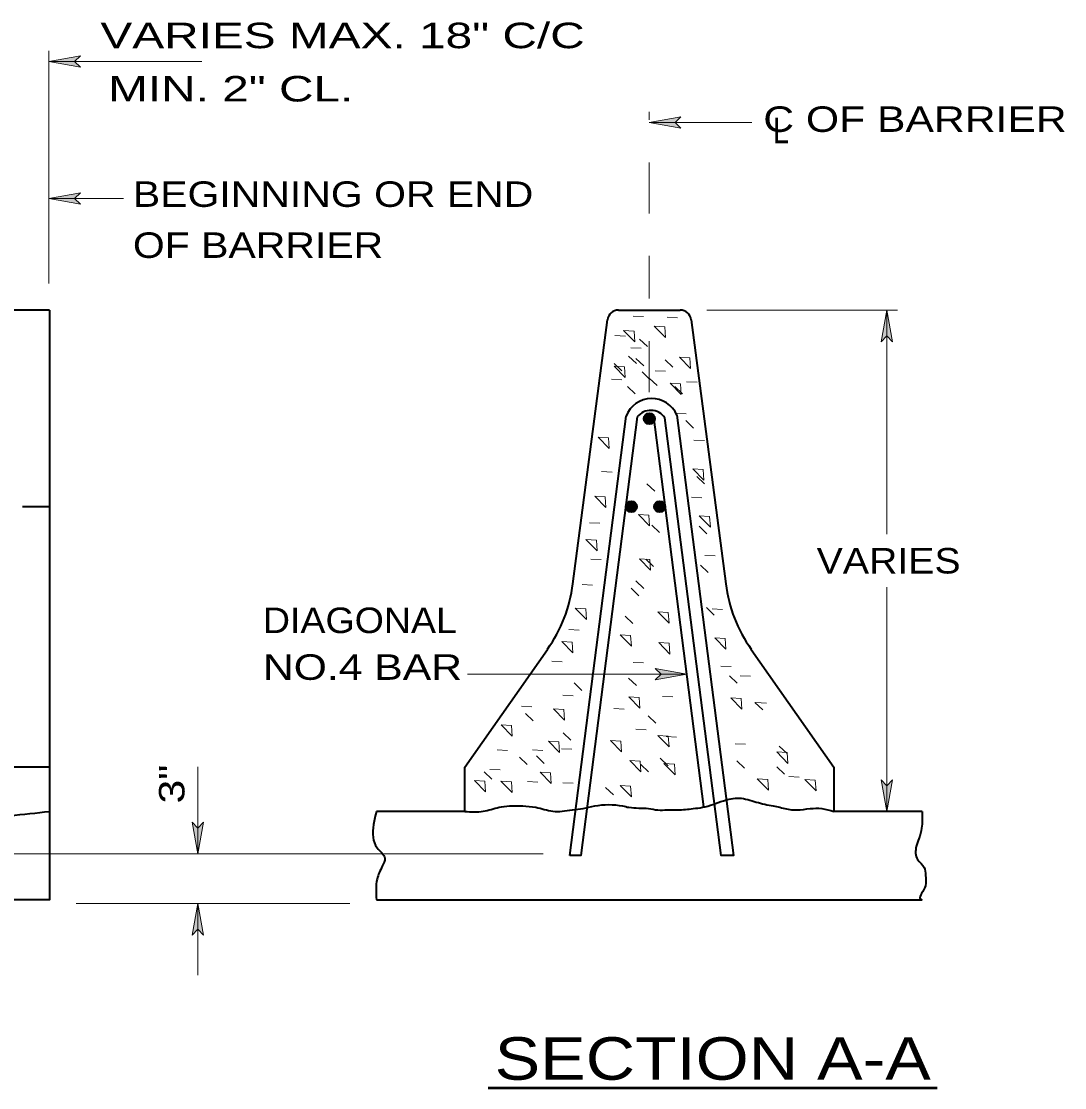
# Model space of a CAD drawing. Extents: x -111.57 to -104.56, y -202.94 to -194.51.
# Drawn here: x -107.008 to -104.555, y -197.601 to -195.094 of the extents above; entities that cross this region are included whole.
import ezdxf
from ezdxf.enums import TextEntityAlignment as Align

# ---------------------------------------------------------------- set-up
doc = ezdxf.new("R2010")
doc.units = 0
doc.header["$LTSCALE"] = 0.024
doc.linetypes.add('DOT_DASHED', pattern=[7.7, 5, -1.2, 0.3, -1.2])
for name, color, linetype, lineweight in [('1', 7, 'Continuous', 35), ('10', 7, 'Continuous', 13), ('12', 7, 'Continuous', 53), ('6', 7, 'Continuous', 13)]:
    doc.layers.add(name, color=color, linetype=linetype, lineweight=lineweight)

msp = doc.modelspace()

# ---------------------------------------------------------------- hatches: boundary and pattern name
at = {"layer": '1'}
for points in [[(-105.51865, -196.02796, 1), (-105.54452, -196.02796, 1)], [(-105.56086, -196.235, 1), (-105.58672, -196.235, 1)], [(-105.49432, -196.235, 1), (-105.52018, -196.235, 1)]]:
    msp.add_hatch(color=256, dxfattribs=at).paths.add_polyline_path(points)
at = {"layer": '10'}
for points in [[(-106.86883, -195.20133), (-106.94333, -195.18817), (-106.86883, -195.175), (-106.883, -195.18817)], [(-105.45717, -195.3445), (-105.53167, -195.33133), (-105.45717, -195.31817), (-105.47117, -195.33133)], [(-106.86883, -195.5235), (-106.94333, -195.51033), (-106.86883, -195.49717), (-106.883, -195.51033)], [(-104.98633, -195.847), (-104.97317, -195.77267), (-104.96, -195.847), (-104.97317, -195.833)], [(-105.518, -196.61567), (-105.4435, -196.62883), (-105.518, -196.642), (-105.504, -196.62883)], [(-104.98633, -196.87717), (-104.97317, -196.95167), (-104.96, -196.87717), (-104.97317, -196.89133)], [(-106.58, -196.97717), (-106.593, -197.05167), (-106.60617, -196.97717), (-106.593, -196.99117)], [(-106.60617, -197.24233), (-106.593, -197.168), (-106.58, -197.24233), (-106.593, -197.22833)]]:
    msp.add_hatch(color=256, dxfattribs=at).paths.add_polyline_path(points)

# ---------------------------------------------------------------- linework, layer by layer
at = {"layer": '1'}
for p, q in [((-106.9415, -195.77267), (-111.493, -195.77267)), ((-105.60417, -195.77267), (-105.459, -195.77267)), ((-105.71133, -196.41667), (-105.63, -195.79533)), ((-105.43317, -195.79533), (-105.35183, -196.4165)), ((-105.71883, -197.05567), (-105.58617, -196.022)), ((-106.9415, -196.235), (-107.00533, -196.235)), ((-106.9415, -196.84767), (-111.493, -196.84767)), ((-105.96517, -196.95167), (-106.17317, -196.95167)), ((-104.89017, -196.95167), (-105.09817, -196.95167)), ((-106.17317, -197.15983), (-104.89017, -197.15983))]:
    msp.add_line(p, q, dxfattribs=at)
for points in [[(-106.9415, -195.77267), (-106.9415, -197.15983), (-111.493, -197.15983)], [(-105.56, -196.024), (-105.6925, -197.05567), (-105.71883, -197.05567)], [(-105.46683, -196.01967), (-105.33383, -197.05567), (-105.36283, -197.05567), (-105.495, -196.02617)], [(-105.96517, -196.95167), (-105.96517, -196.84767), (-105.77117, -196.5705)], [(-105.29217, -196.5705), (-105.09817, -196.84767), (-105.09817, -196.95167)]]:
    msp.add_lwpolyline(points, dxfattribs=at)
for centre in [(-105.53158, -196.02796), (-105.57379, -196.235), (-105.50725, -196.235)]:
    msp.add_circle(centre, 0.01293, dxfattribs=at)
for centre, radius, start, end in [((-105.60414, -195.79863), 0.02601, 90, 172.54564), ((-105.45906, -195.79863), 0.02601, 7.46293, 90), ((-105.526, -196.04516), 0.06446, 23.1931, 158.88304), ((-105.52831, -196.04879), 0.04024, 34.0471, 142.14754), ((-106.05514, -196.3716), 0.34678, 325.01261, 352.53254), ((-105.00805, -196.37159), 0.34678, 187.4588, 214.99795)]:
    msp.add_arc(centre, radius, start, end, dxfattribs=at)
for points in [[(-110.89483, -196.95167), (-110.80983, -196.9485), (-110.77133, -196.93583), (-110.73283, -196.9315), (-110.70733, -196.94417), (-110.68167, -196.95267), (-110.66033, -196.95267), (-110.639, -196.9485), (-110.61333, -196.94417), (-110.5835, -196.94), (-110.54933, -196.94), (-110.528, -196.94), (-110.50667, -196.9485), (-110.45967, -196.9485), (-110.42117, -196.9485), (-110.36567, -196.93583), (-110.323, -196.9315), (-110.29317, -196.92717), (-110.28033, -196.94), (-110.2505, -196.95267), (-110.19483, -196.95267), (-110.15217, -196.9485), (-110.08817, -196.93583), (-110.02417, -196.92717), (-109.99417, -196.9315), (-109.96433, -196.94), (-109.88317, -196.9485), (-109.84483, -196.94417), (-109.81483, -196.93583), (-109.768, -196.92717), (-109.704, -196.923), (-109.67817, -196.92717), (-109.6185, -196.93583), (-109.56717, -196.94417), (-109.49033, -196.9485), (-109.42633, -196.95267), (-109.34517, -196.94417), (-109.28967, -196.94417), (-109.22567, -196.9315), (-109.1615, -196.923), (-109.11033, -196.923), (-109.02067, -196.93583), (-108.93533, -196.94417), (-108.8585, -196.9485), (-108.773, -196.9485), (-108.70467, -196.9485), (-108.615, -196.94), (-108.52967, -196.92717), (-108.46133, -196.9145), (-108.376, -196.9315), (-108.30767, -196.94), (-108.21783, -196.94417), (-108.1155, -196.94), (-108.03433, -196.93583), (-107.966, -196.9315), (-107.902, -196.92717), (-107.82083, -196.91867), (-107.76533, -196.92717), (-107.71833, -196.93583), (-107.63717, -196.94417), (-107.54333, -196.94), (-107.50483, -196.9315), (-107.45367, -196.923), (-107.411, -196.923), (-107.31267, -196.9315), (-107.23583, -196.94417), (-107.159, -196.96117), (-107.03517, -196.96117), (-106.9415, -196.95167)], [(-105.96517, -196.95167), (-105.922, -196.95117), (-105.88483, -196.942), (-105.86033, -196.93883), (-105.82933, -196.93883), (-105.7985, -196.942), (-105.75833, -196.95117), (-105.73683, -196.95117), (-105.71217, -196.94817), (-105.68733, -196.945), (-105.65967, -196.93883), (-105.59483, -196.93883), (-105.5795, -196.942), (-105.53317, -196.945), (-105.51167, -196.94817), (-105.49, -196.94817), (-105.46533, -196.94817), (-105.42833, -196.945), (-105.40667, -196.942), (-105.35733, -196.92667), (-105.32033, -196.92033), (-105.28017, -196.92967), (-105.24017, -196.93883), (-105.22467, -196.942), (-105.19383, -196.94817), (-105.18467, -196.94817), (-105.15367, -196.945), (-105.126, -196.945), (-105.09817, -196.95167)]]:
    msp.add_spline(points, degree=3, dxfattribs=at)
at = {"layer": '10'}
for p, q in [((-106.94333, -195.71017), (-106.94333, -195.16317)), ((-106.94333, -195.18817), (-106.86883, -195.175)), ((-106.94333, -195.18817), (-106.58333, -195.18817)), ((-106.94333, -195.18817), (-106.86883, -195.20133)), ((-105.53167, -195.33133), (-105.45717, -195.31817)), ((-105.29067, -195.33133), (-105.53167, -195.33133)), ((-105.53167, -195.33133), (-105.45717, -195.3445)), ((-106.94333, -195.51033), (-106.86883, -195.49717)), ((-106.94333, -195.51033), (-106.76817, -195.51033)), ((-106.94333, -195.51033), (-106.86883, -195.5235)), ((-105.3965, -195.77267), (-104.94817, -195.77267)), ((-104.97317, -195.77267), (-104.98633, -195.847)), ((-104.97317, -195.77267), (-104.96, -195.847)), ((-104.97317, -196.29967), (-104.97317, -195.77267)), ((-104.97317, -196.95167), (-104.97317, -196.42467)), ((-105.4435, -196.62883), (-105.518, -196.61567)), ((-105.959, -196.62883), (-105.4435, -196.62883)), ((-105.4435, -196.62883), (-105.518, -196.642)), ((-106.593, -197.05167), (-106.593, -196.84683)), ((-104.97317, -196.95167), (-104.98633, -196.87717)), ((-104.97317, -196.95167), (-104.96, -196.87717)), ((-106.593, -197.05167), (-106.60617, -196.97717)), ((-106.593, -197.05167), (-106.58, -196.97717)), ((-107.08717, -197.05167), (-105.78133, -197.05167)), ((-106.879, -197.168), (-106.23567, -197.168)), ((-106.593, -197.168), (-106.60617, -197.24233)), ((-106.593, -197.168), (-106.593, -197.33667)), ((-106.593, -197.168), (-106.58, -197.24233))]:
    msp.add_line(p, q, dxfattribs=at)
at = {"layer": '10', "linetype": 'DOT_DASHED'}
msp.add_line((-105.53167, -195.9655), (-105.53167, -195.30633), dxfattribs=at)
at = {"layer": '10', "lineweight": 35}
msp.add_line((-105.4035, -196.94117), (-105.52183, -196.01733), dxfattribs=at)
at = {"layer": '10'}
for points in [[(-106.86883, -195.20133), (-106.94333, -195.18817), (-106.86883, -195.175), (-106.883, -195.18817)], [(-105.45717, -195.3445), (-105.53167, -195.33133), (-105.45717, -195.31817), (-105.47117, -195.33133)], [(-106.86883, -195.5235), (-106.94333, -195.51033), (-106.86883, -195.49717), (-106.883, -195.51033)], [(-104.98633, -195.847), (-104.97317, -195.77267), (-104.96, -195.847), (-104.97317, -195.833)], [(-105.518, -196.61567), (-105.4435, -196.62883), (-105.518, -196.642), (-105.504, -196.62883)], [(-104.98633, -196.87717), (-104.97317, -196.95167), (-104.96, -196.87717), (-104.97317, -196.89133)], [(-106.58, -196.97717), (-106.593, -197.05167), (-106.60617, -196.97717), (-106.593, -196.99117)], [(-106.60617, -197.24233), (-106.593, -197.168), (-106.58, -197.24233), (-106.593, -197.22833)]]:
    msp.add_lwpolyline(points, close=True, dxfattribs=at)
for points in [[(-106.86883, -195.20133), (-106.883, -195.18817), (-106.86883, -195.175)], [(-105.45717, -195.3445), (-105.47117, -195.33133), (-105.45717, -195.31817)], [(-106.86883, -195.5235), (-106.883, -195.51033), (-106.86883, -195.49717)], [(-104.98633, -195.847), (-104.97317, -195.833), (-104.96, -195.847)], [(-105.518, -196.61567), (-105.504, -196.62883), (-105.518, -196.642)], [(-104.98633, -196.87717), (-104.97317, -196.89133), (-104.96, -196.87717)], [(-106.58, -196.97717), (-106.593, -196.99117), (-106.60617, -196.97717)], [(-106.60617, -197.24233), (-106.593, -197.22833), (-106.58, -197.24233)]]:
    msp.add_lwpolyline(points, dxfattribs=at)
at = {"layer": '10', "lineweight": 35}
for points in [[(-106.17317, -196.95167), (-106.181, -197.01267), (-106.17167, -197.03717), (-106.15333, -197.06183), (-106.15933, -197.08033), (-106.17167, -197.111), (-106.17317, -197.15983)], [(-104.89017, -196.95167), (-104.8915, -196.99117), (-104.89767, -197.01583), (-104.904, -197.03417), (-104.90083, -197.06483), (-104.88533, -197.08333), (-104.88233, -197.10183), (-104.88233, -197.1265), (-104.8915, -197.14483), (-104.89467, -197.15717), (-104.89017, -197.15983)]]:
    msp.add_spline(points, degree=3, dxfattribs=at)
at = {"layer": '12'}
msp.add_line((-105.91017, -197.60133), (-104.855, -197.60133), dxfattribs=at)
at = {"layer": '6'}
for p, q in [((-105.545, -195.788), (-105.5695, -195.78683)), ((-105.465, -195.79083), (-105.4895, -195.78967)), ((-105.58783, -195.83383), (-105.61233, -195.83267)), ((-105.53617, -195.8585), (-105.5545, -195.841)), ((-105.55067, -195.86233), (-105.57517, -195.86117)), ((-105.59617, -195.91567), (-105.6145, -195.89817)), ((-105.56183, -195.8985), (-105.58017, -195.881)), ((-105.54467, -195.90417), (-105.563, -195.88667)), ((-105.47617, -195.90717), (-105.4945, -195.88967)), ((-105.5305, -195.93567), (-105.54867, -195.91817)), ((-105.49367, -195.91667), (-105.518, -195.9155)), ((-105.5965, -195.93667), (-105.62083, -195.9355)), ((-105.51333, -195.95), (-105.53167, -195.9325)), ((-105.41933, -195.94233), (-105.44383, -195.94117)), ((-105.56467, -195.97), (-105.583, -195.9525)), ((-105.45333, -195.97), (-105.47167, -195.9525)), ((-105.445, -196.01667), (-105.4695, -196.0155)), ((-105.42767, -196.05), (-105.446, -196.0325)), ((-105.40217, -196.0795), (-105.42667, -196.07833)), ((-105.61933, -196.15383), (-105.64367, -196.15267)), ((-105.402, -196.1815), (-105.42017, -196.164)), ((-105.519, -196.1985), (-105.53733, -196.181)), ((-105.408, -196.21383), (-105.43233, -196.21267)), ((-105.64783, -196.27383), (-105.67217, -196.27267)), ((-105.50767, -196.29567), (-105.52583, -196.27817)), ((-105.39617, -196.29867), (-105.4145, -196.28117)), ((-105.3765, -196.351), (-105.401, -196.34983)), ((-105.645, -196.3595), (-105.66933, -196.35833)), ((-105.52183, -196.37567), (-105.54017, -196.35817)), ((-105.39333, -196.39), (-105.41167, -196.3725)), ((-105.665, -196.4195), (-105.68933, -196.41833)), ((-105.55617, -196.44433), (-105.5745, -196.42683)), ((-105.54467, -196.42717), (-105.563, -196.40967)), ((-105.379, -196.49), (-105.39733, -196.4725)), ((-105.35933, -196.47667), (-105.38383, -196.4755)), ((-105.5705, -196.51), (-105.58867, -196.4925)), ((-105.69633, -196.52533), (-105.72083, -196.52417)), ((-105.73633, -196.59967), (-105.76083, -196.5985)), ((-105.545, -196.6025), (-105.5695, -196.60133)), ((-105.33933, -196.611), (-105.36383, -196.60983)), ((-105.69033, -196.66717), (-105.70867, -196.64967)), ((-105.56183, -196.65583), (-105.58017, -196.63833)), ((-105.32483, -196.65), (-105.34317, -196.6325)), ((-105.29367, -196.63383), (-105.31817, -196.63267)), ((-105.71067, -196.67967), (-105.735, -196.6785)), ((-105.4765, -196.6825), (-105.50083, -196.68133)), ((-105.26483, -196.713), (-105.28317, -196.6955)), ((-105.2565, -196.69683), (-105.281, -196.69567)), ((-105.80783, -196.70533), (-105.83217, -196.70417)), ((-105.80467, -196.73867), (-105.82283, -196.72117)), ((-105.59067, -196.711), (-105.61517, -196.70983)), ((-105.51617, -196.74433), (-105.5345, -196.72683)), ((-105.716, -196.78433), (-105.73433, -196.76683)), ((-105.53933, -196.75967), (-105.56367, -196.7585)), ((-105.46783, -196.77683), (-105.49233, -196.77567)), ((-105.30517, -196.79383), (-105.3295, -196.79267)), ((-105.20767, -196.81583), (-105.226, -196.79833)), ((-105.86483, -196.80817), (-105.88933, -196.807)), ((-105.81883, -196.8415), (-105.83717, -196.824)), ((-105.782, -196.80817), (-105.8065, -196.807)), ((-105.77883, -196.83867), (-105.79717, -196.82117)), ((-105.7135, -196.80533), (-105.738, -196.80417)), ((-105.48767, -196.84433), (-105.50583, -196.82683)), ((-105.882, -196.854), (-105.9065, -196.85283)), ((-105.53333, -196.85867), (-105.55167, -196.84117)), ((-105.30767, -196.85017), (-105.326, -196.83267)), ((-105.2135, -196.86433), (-105.23167, -196.84683)), ((-105.90167, -196.87583), (-105.92, -196.85833)), ((-105.1795, -196.871), (-105.20383, -196.86983)), ((-105.7935, -196.8825), (-105.81783, -196.88133)), ((-105.71067, -196.88533), (-105.735, -196.88417)), ((-105.61617, -196.913), (-105.63433, -196.8955))]:
    msp.add_line(p, q, dxfattribs=at)
for points in [[(-105.5675, -195.822), (-105.592, -195.82033), (-105.56583, -195.847)], [(-105.4955, -195.812), (-105.52, -195.81033), (-105.49383, -195.83717)], [(-105.43617, -195.88483), (-105.46067, -195.88317), (-105.4345, -195.91)], [(-105.58967, -195.90633), (-105.61417, -195.90467), (-105.58817, -195.9315)], [(-105.45833, -195.94633), (-105.48283, -195.94467), (-105.45667, -195.9715)], [(-105.6275, -196.0735), (-105.652, -196.07183), (-105.62583, -196.0985)], [(-105.40467, -196.14767), (-105.42917, -196.14617), (-105.40317, -196.17283)], [(-105.6355, -196.212), (-105.66, -196.2105), (-105.63383, -196.23717)], [(-105.53267, -196.255), (-105.55717, -196.25333), (-105.531, -196.28)], [(-105.38983, -196.25783), (-105.41433, -196.25617), (-105.38817, -196.283)], [(-105.656, -196.3135), (-105.6805, -196.31183), (-105.65433, -196.3385)], [(-105.53033, -196.35917), (-105.55483, -196.3575), (-105.52867, -196.38433)], [(-105.68117, -196.475), (-105.70567, -196.47333), (-105.6795, -196.50017)], [(-105.487, -196.4835), (-105.5115, -196.482), (-105.48533, -196.50867)], [(-105.71317, -196.5535), (-105.73767, -196.55183), (-105.7115, -196.57867)], [(-105.5755, -196.53783), (-105.6, -196.53617), (-105.57383, -196.563)], [(-105.35333, -196.545), (-105.37783, -196.54333), (-105.35167, -196.57)], [(-105.48467, -196.55633), (-105.50917, -196.55467), (-105.483, -196.5815)], [(-105.5555, -196.6835), (-105.58, -196.682), (-105.55383, -196.70867)], [(-105.3155, -196.6865), (-105.34, -196.68483), (-105.314, -196.7115)], [(-105.7325, -196.71217), (-105.757, -196.7105), (-105.73083, -196.73733)], [(-105.85533, -196.74933), (-105.87983, -196.74767), (-105.85367, -196.7745)], [(-105.487, -196.775), (-105.5115, -196.77333), (-105.48533, -196.80017)], [(-105.7445, -196.78783), (-105.769, -196.78617), (-105.743, -196.813)], [(-105.59833, -196.7865), (-105.62283, -196.78483), (-105.59667, -196.8115)], [(-105.20767, -196.8135), (-105.23217, -196.81183), (-105.206, -196.83867)], [(-105.55317, -196.8335), (-105.57767, -196.83183), (-105.55167, -196.85867)], [(-105.47267, -196.84067), (-105.49717, -196.83917), (-105.471, -196.86583)], [(-105.764, -196.86067), (-105.7885, -196.85917), (-105.76233, -196.88583)], [(-105.25333, -196.87633), (-105.27783, -196.87483), (-105.25167, -196.9015)], [(-105.14133, -196.87783), (-105.16583, -196.87633), (-105.13967, -196.903)], [(-105.91817, -196.88083), (-105.94267, -196.87917), (-105.9165, -196.90583)], [(-105.856, -196.88217), (-105.8805, -196.8805), (-105.85433, -196.90717)], [(-105.5755, -196.89217), (-105.6, -196.8905), (-105.57383, -196.91733)]]:
    msp.add_lwpolyline(points, close=True, dxfattribs=at)

# ---------------------------------------------------------------- texts
at = {"layer": '12'}
for s, width, p in [('VARIES MAX. 18" C/C', 1.4, (-106.82208, -195.15683)), ('MIN. 2" CL.', 1.4, (-106.80408, -195.28217)), ('C OF BARRIER', 1.25, (-105.26375, -195.35367)), ('L', 0.85, (-105.24125, -195.3805)), ('BEGINNING OR END', 1.2, (-106.74575, -195.53)), ('OF BARRIER', 1.2, (-106.74575, -195.65)), ('DIAGONAL', 1.1, (-106.44008, -196.53225)), ('NO.4 BAR', 1.25, (-106.44008, -196.64225))]:
    msp.add_text(s, height=0.06, dxfattribs=dict(at, width=width)).set_placement(p)
for s, height, width, p in [('VARIES', 0.06, 1.15, (-104.96896, -196.39217)), ('SECTION A-A', 0.1, 1.2, (-105.3825, -197.58267))]:
    msp.add_text(s, height=height, dxfattribs=dict(at, width=width)).set_placement(p, align=Align.CENTER)
at = {"layer": '12', "width": 1.25}
msp.add_text('3"', height=0.06, rotation=90, dxfattribs=at).set_placement((-106.62442, -196.933))

doc.saveas('drawing.dxf')
